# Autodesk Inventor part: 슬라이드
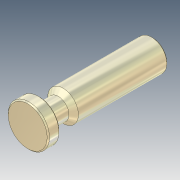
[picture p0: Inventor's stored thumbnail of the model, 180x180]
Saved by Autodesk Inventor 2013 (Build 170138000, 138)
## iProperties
Company: 한국ATC센터
Created: 2014-11
Part Number: 슬라이드
Document SubType Name: Modeling
Designer: KYOUNG IL JANG
Density: 7.86 g/cm^3
Material: Steel, Mild
Mass: 436.103 g
Surface Area: 105.764 cm^2
Volume: 55.4838 cm^3
Author: KYOUNG IL JANG
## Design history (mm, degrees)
revolve "회전1" stored, may be unused: angle "d6" = 90 deg
chamfer "모따기1" distance "d7" = 1; stored, may be unused: second distance "d8" = 2, angle "d9" = 45 deg
fillet "모깎기1" dims "d10" = 2
node "솔리드1"
sketch "스케치1"
  geometry: L1 (19, 106.5)-(-19, 106.5) reference; L2 (0, 106.5)-(0, 212.5); L3 (0, 212.5)-(-13, 212.5); L4 (-13, 212.5)-(-13, 136.5); L5 (-9, 116.5)-(-17.5, 116.5); L6 (-17.5, 116.5)-(-17.5, 106.5); L7 (-17.5, 106.5)-(0, 106.5); L8 (-9, 116.5)-(-9, 132.5); L9 (-9, 132.5)-(-13, 136.5); 1 further point
  constraints: 18 end point, 3 perpendicular, 1 collinear, 1 horizontal, 1 midpoint, 1 parallel, 2 other
  dimensions: "d0" = 10 distance between parallel lines of L5 L7; "d1" = 35 diameter of L6 L2; "d2" = 106 distance of L2.start L2.end; "d3" = 135 deg angle of L9 L4; "d4" = 18 diameter of L8 L2; "d5" = 30 distance from line of L4.end L7; "d11" = 26 diameter of L4 L2
